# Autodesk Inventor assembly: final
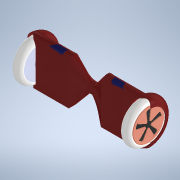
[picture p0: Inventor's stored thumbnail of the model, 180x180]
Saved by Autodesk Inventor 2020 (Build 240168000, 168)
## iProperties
Created: 2017-04
Part Number: final
Document SubType Name: Assembly
Designer: bruno
Author: bruno
Sending System: SolidWorks 2016
Last Author: Samartha
Last Saved: 2017-04-03
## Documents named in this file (4)
- C:\Users\bruno\Downloads\segway-hoverboard-1.snapshot.1\segway\final.iam
- C:\Users\bruno\Downloads\segway-hoverboard-1.snapshot.1\segway\body.ipt
- C:\Users\bruno\Downloads\segway-hoverboard-1.snapshot.1\segway\pad.ipt
- C:\Users\bruno\Downloads\segway-hoverboard-1.snapshot.1\segway\tire.ipt
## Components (5 placed, 3 different names)
1. body:1
2. pad:1
3. pad:2
4. tire:1
5. tire:2
